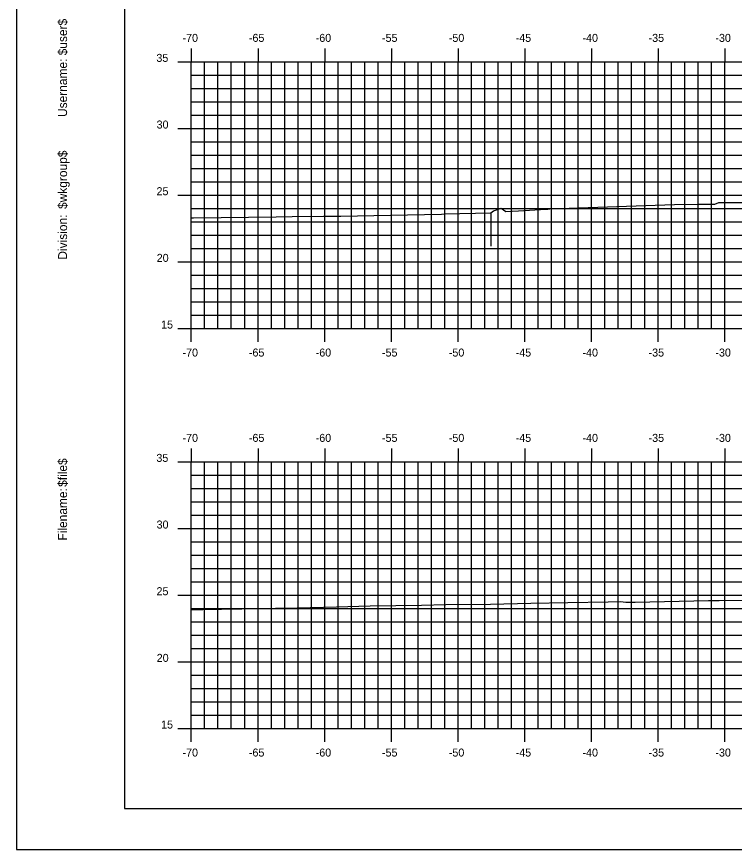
# Model space of a CAD drawing. Extents: x 1023237 to 1023407, y 394697 to 394807.
# Drawn here: x 1023236.6 to 1023290.4, y 394696.5 to 394759 of the extents above; entities that cross this region are included whole.
import ezdxf

# ---------------------------------------------------------------- set-up
doc = ezdxf.new("R2010")
doc.units = 0
for name, color, linetype in [('BORDER', 7, 'Continuous'), ('H_V ANNOTATION', 7, 'Continuous'), ('MAJOR', 7, 'Continuous'), ('MINOR', 7, 'Continuous'), ('PLOT BOUNDARY', 7, 'Continuous'), ('S_Roadway_Centerline', 7, 'Continuous'), ('S_Roadway_Edge_Pavement', 7, 'Continuous')]:
    doc.layers.add(name, color=color, linetype=linetype)

msp = doc.modelspace()

# ---------------------------------------------------------------- linework, layer by layer
at = {"layer": 'BORDER'}
for p, q in [((1023244.664, 394804.607), (1023244.664, 394699.607)), ((1023244.664, 394699.607), (1023404.664, 394699.607))]:
    msp.add_line(p, q, dxfattribs=at)
at = {"layer": 'MAJOR'}
for p, q in [((1023249.663, 394756.609), (1023249.663, 394755.607)), ((1023254.663, 394756.609), (1023254.663, 394755.607)), ((1023259.663, 394756.609), (1023259.663, 394755.607)), ((1023264.663, 394756.609), (1023264.663, 394755.607)), ((1023269.663, 394756.609), (1023269.663, 394755.607)), ((1023274.663, 394756.609), (1023274.663, 394755.607)), ((1023279.663, 394756.609), (1023279.663, 394755.607)), ((1023284.663, 394756.609), (1023284.663, 394755.607)), ((1023289.663, 394756.609), (1023289.663, 394755.607)), ((1023248.661, 394755.607), (1023249.663, 394755.607)), ((1023249.663, 394755.607), (1023389.663, 394755.607)), ((1023249.663, 394735.607), (1023249.663, 394755.607)), ((1023254.663, 394735.607), (1023254.663, 394755.607)), ((1023259.663, 394735.607), (1023259.663, 394755.607)), ((1023264.663, 394735.607), (1023264.663, 394755.607)), ((1023269.663, 394735.607), (1023269.663, 394755.607)), ((1023274.663, 394735.607), (1023274.663, 394755.607)), ((1023279.663, 394735.607), (1023279.663, 394755.607)), ((1023284.663, 394735.607), (1023284.663, 394755.607)), ((1023289.663, 394735.607), (1023289.663, 394755.607)), ((1023248.661, 394750.607), (1023249.663, 394750.607)), ((1023249.663, 394750.607), (1023389.663, 394750.607)), ((1023248.661, 394745.607), (1023249.663, 394745.607)), ((1023249.663, 394745.607), (1023389.663, 394745.607)), ((1023248.661, 394740.607), (1023249.663, 394740.607)), ((1023249.663, 394740.607), (1023389.663, 394740.607)), ((1023248.661, 394735.607), (1023249.663, 394735.607)), ((1023249.663, 394735.607), (1023389.663, 394735.607)), ((1023249.663, 394734.605), (1023249.663, 394735.607)), ((1023254.663, 394734.605), (1023254.663, 394735.607)), ((1023259.663, 394734.605), (1023259.663, 394735.607)), ((1023264.663, 394734.605), (1023264.663, 394735.607)), ((1023269.663, 394734.605), (1023269.663, 394735.607)), ((1023274.663, 394734.605), (1023274.663, 394735.607)), ((1023279.663, 394734.605), (1023279.663, 394735.607)), ((1023284.663, 394734.605), (1023284.663, 394735.607)), ((1023289.663, 394734.605), (1023289.663, 394735.607)), ((1023249.663, 394726.609), (1023249.663, 394725.607)), ((1023254.663, 394726.609), (1023254.663, 394725.607)), ((1023259.663, 394726.609), (1023259.663, 394725.607)), ((1023264.663, 394726.609), (1023264.663, 394725.607)), ((1023269.663, 394726.609), (1023269.663, 394725.607)), ((1023274.663, 394726.609), (1023274.663, 394725.607)), ((1023279.663, 394726.609), (1023279.663, 394725.607)), ((1023284.663, 394726.609), (1023284.663, 394725.607)), ((1023289.663, 394726.609), (1023289.663, 394725.607)), ((1023248.661, 394725.607), (1023249.663, 394725.607)), ((1023249.663, 394725.607), (1023389.663, 394725.607)), ((1023249.663, 394705.607), (1023249.663, 394725.607)), ((1023254.663, 394705.607), (1023254.663, 394725.607)), ((1023259.663, 394705.607), (1023259.663, 394725.607)), ((1023264.663, 394705.607), (1023264.663, 394725.607)), ((1023269.663, 394705.607), (1023269.663, 394725.607)), ((1023274.663, 394705.607), (1023274.663, 394725.607)), ((1023279.663, 394705.607), (1023279.663, 394725.607)), ((1023284.663, 394705.607), (1023284.663, 394725.607)), ((1023289.663, 394705.607), (1023289.663, 394725.607)), ((1023248.661, 394720.607), (1023249.663, 394720.607)), ((1023249.663, 394720.607), (1023389.663, 394720.607)), ((1023248.661, 394715.607), (1023249.663, 394715.607)), ((1023249.663, 394715.607), (1023389.663, 394715.607)), ((1023248.661, 394710.607), (1023249.663, 394710.607)), ((1023249.663, 394710.607), (1023389.663, 394710.607)), ((1023248.661, 394705.607), (1023249.663, 394705.607)), ((1023249.663, 394705.607), (1023389.663, 394705.607)), ((1023249.663, 394704.605), (1023249.663, 394705.607)), ((1023254.663, 394704.605), (1023254.663, 394705.607)), ((1023259.663, 394704.605), (1023259.663, 394705.607)), ((1023264.663, 394704.605), (1023264.663, 394705.607)), ((1023269.663, 394704.605), (1023269.663, 394705.607)), ((1023274.663, 394704.605), (1023274.663, 394705.607)), ((1023279.663, 394704.605), (1023279.663, 394705.607)), ((1023284.663, 394704.605), (1023284.663, 394705.607)), ((1023289.663, 394704.605), (1023289.663, 394705.607))]:
    msp.add_line(p, q, dxfattribs=at)
at = {"layer": 'MINOR'}
for p, q in [((1023250.663, 394735.607), (1023250.663, 394755.607)), ((1023251.663, 394735.607), (1023251.663, 394755.607)), ((1023252.663, 394735.607), (1023252.663, 394755.607)), ((1023253.663, 394735.607), (1023253.663, 394755.607)), ((1023255.663, 394735.607), (1023255.663, 394755.607)), ((1023256.663, 394735.607), (1023256.663, 394755.607)), ((1023257.663, 394735.607), (1023257.663, 394755.607)), ((1023258.663, 394735.607), (1023258.663, 394755.607)), ((1023260.663, 394735.607), (1023260.663, 394755.607)), ((1023261.663, 394735.607), (1023261.663, 394755.607)), ((1023262.663, 394735.607), (1023262.663, 394755.607)), ((1023263.663, 394735.607), (1023263.663, 394755.607)), ((1023265.663, 394735.607), (1023265.663, 394755.607)), ((1023266.663, 394735.607), (1023266.663, 394755.607)), ((1023267.663, 394735.607), (1023267.663, 394755.607)), ((1023268.663, 394735.607), (1023268.663, 394755.607)), ((1023270.663, 394735.607), (1023270.663, 394755.607)), ((1023271.663, 394735.607), (1023271.663, 394755.607)), ((1023272.663, 394735.607), (1023272.663, 394755.607)), ((1023273.663, 394735.607), (1023273.663, 394755.607)), ((1023275.663, 394735.607), (1023275.663, 394755.607)), ((1023276.663, 394735.607), (1023276.663, 394755.607)), ((1023277.663, 394735.607), (1023277.663, 394755.607)), ((1023278.663, 394735.607), (1023278.663, 394755.607)), ((1023280.663, 394735.607), (1023280.663, 394755.607)), ((1023281.663, 394735.607), (1023281.663, 394755.607)), ((1023282.663, 394735.607), (1023282.663, 394755.607)), ((1023283.663, 394735.607), (1023283.663, 394755.607)), ((1023285.663, 394735.607), (1023285.663, 394755.607)), ((1023286.663, 394735.607), (1023286.663, 394755.607)), ((1023287.663, 394735.607), (1023287.663, 394755.607)), ((1023288.663, 394735.607), (1023288.663, 394755.607)), ((1023249.663, 394754.607), (1023389.663, 394754.607)), ((1023249.663, 394754.607), (1023250.665, 394754.607)), ((1023249.663, 394753.607), (1023389.663, 394753.607)), ((1023249.663, 394753.607), (1023250.665, 394753.607)), ((1023249.663, 394752.607), (1023389.663, 394752.607)), ((1023249.663, 394752.607), (1023250.665, 394752.607)), ((1023249.663, 394751.607), (1023389.663, 394751.607)), ((1023249.663, 394751.607), (1023250.665, 394751.607)), ((1023249.663, 394749.607), (1023389.663, 394749.607)), ((1023249.663, 394749.607), (1023250.665, 394749.607)), ((1023249.663, 394748.607), (1023389.663, 394748.607)), ((1023249.663, 394748.607), (1023250.665, 394748.607)), ((1023249.663, 394747.607), (1023389.663, 394747.607)), ((1023249.663, 394747.607), (1023250.665, 394747.607)), ((1023249.663, 394746.607), (1023389.663, 394746.607)), ((1023249.663, 394746.607), (1023250.665, 394746.607)), ((1023249.663, 394744.607), (1023389.663, 394744.607)), ((1023249.663, 394744.607), (1023250.665, 394744.607)), ((1023249.663, 394743.607), (1023389.663, 394743.607)), ((1023249.663, 394743.607), (1023250.665, 394743.607)), ((1023249.663, 394742.607), (1023389.663, 394742.607)), ((1023249.663, 394742.607), (1023250.665, 394742.607)), ((1023249.663, 394741.607), (1023389.663, 394741.607)), ((1023249.663, 394741.607), (1023250.665, 394741.607)), ((1023249.663, 394739.607), (1023389.663, 394739.607)), ((1023249.663, 394739.607), (1023250.665, 394739.607)), ((1023249.663, 394738.607), (1023389.663, 394738.607)), ((1023249.663, 394738.607), (1023250.665, 394738.607)), ((1023249.663, 394737.607), (1023389.663, 394737.607)), ((1023249.663, 394737.607), (1023250.665, 394737.607)), ((1023249.663, 394736.607), (1023389.663, 394736.607)), ((1023249.663, 394736.607), (1023250.665, 394736.607)), ((1023250.663, 394705.607), (1023250.663, 394725.607)), ((1023251.663, 394705.607), (1023251.663, 394725.607)), ((1023252.663, 394705.607), (1023252.663, 394725.607)), ((1023253.663, 394705.607), (1023253.663, 394725.607)), ((1023255.663, 394705.607), (1023255.663, 394725.607)), ((1023256.663, 394705.607), (1023256.663, 394725.607)), ((1023257.663, 394705.607), (1023257.663, 394725.607)), ((1023258.663, 394705.607), (1023258.663, 394725.607)), ((1023260.663, 394705.607), (1023260.663, 394725.607)), ((1023261.663, 394705.607), (1023261.663, 394725.607)), ((1023262.663, 394705.607), (1023262.663, 394725.607)), ((1023263.663, 394705.607), (1023263.663, 394725.607)), ((1023265.663, 394705.607), (1023265.663, 394725.607)), ((1023266.663, 394705.607), (1023266.663, 394725.607)), ((1023267.663, 394705.607), (1023267.663, 394725.607)), ((1023268.663, 394705.607), (1023268.663, 394725.607)), ((1023270.663, 394705.607), (1023270.663, 394725.607)), ((1023271.663, 394705.607), (1023271.663, 394725.607)), ((1023272.663, 394705.607), (1023272.663, 394725.607)), ((1023273.663, 394705.607), (1023273.663, 394725.607)), ((1023275.663, 394705.607), (1023275.663, 394725.607)), ((1023276.663, 394705.607), (1023276.663, 394725.607)), ((1023277.663, 394705.607), (1023277.663, 394725.607)), ((1023278.663, 394705.607), (1023278.663, 394725.607)), ((1023280.663, 394705.607), (1023280.663, 394725.607)), ((1023281.663, 394705.607), (1023281.663, 394725.607)), ((1023282.663, 394705.607), (1023282.663, 394725.607)), ((1023283.663, 394705.607), (1023283.663, 394725.607)), ((1023285.663, 394705.607), (1023285.663, 394725.607)), ((1023286.663, 394705.607), (1023286.663, 394725.607)), ((1023287.663, 394705.607), (1023287.663, 394725.607)), ((1023288.663, 394705.607), (1023288.663, 394725.607)), ((1023249.663, 394724.607), (1023389.663, 394724.607)), ((1023249.663, 394724.607), (1023250.665, 394724.607)), ((1023249.663, 394723.607), (1023389.663, 394723.607)), ((1023249.663, 394723.607), (1023250.665, 394723.607)), ((1023249.663, 394722.607), (1023389.663, 394722.607)), ((1023249.663, 394722.607), (1023250.665, 394722.607)), ((1023249.663, 394721.607), (1023389.663, 394721.607)), ((1023249.663, 394721.607), (1023250.665, 394721.607)), ((1023249.663, 394719.607), (1023389.663, 394719.607)), ((1023249.663, 394719.607), (1023250.665, 394719.607)), ((1023249.663, 394718.607), (1023389.663, 394718.607)), ((1023249.663, 394718.607), (1023250.665, 394718.607)), ((1023249.663, 394717.607), (1023389.663, 394717.607)), ((1023249.663, 394717.607), (1023250.665, 394717.607)), ((1023249.663, 394716.607), (1023389.663, 394716.607)), ((1023249.663, 394716.607), (1023250.665, 394716.607)), ((1023249.663, 394714.607), (1023389.663, 394714.607)), ((1023249.663, 394714.607), (1023250.665, 394714.607)), ((1023249.663, 394713.607), (1023389.663, 394713.607)), ((1023249.663, 394713.607), (1023250.665, 394713.607)), ((1023249.663, 394712.607), (1023389.663, 394712.607)), ((1023249.663, 394712.607), (1023250.665, 394712.607)), ((1023249.663, 394711.607), (1023389.663, 394711.607)), ((1023249.663, 394711.607), (1023250.665, 394711.607)), ((1023249.663, 394709.607), (1023389.663, 394709.607)), ((1023249.663, 394709.607), (1023250.665, 394709.607)), ((1023249.663, 394708.607), (1023389.663, 394708.607)), ((1023249.663, 394708.607), (1023250.665, 394708.607)), ((1023249.663, 394707.607), (1023389.663, 394707.607)), ((1023249.663, 394707.607), (1023250.665, 394707.607)), ((1023249.663, 394706.607), (1023389.663, 394706.607)), ((1023249.663, 394706.607), (1023250.665, 394706.607))]:
    msp.add_line(p, q, dxfattribs=at)
at = {"layer": 'PLOT BOUNDARY'}
msp.add_lwpolyline([(1023236.57, 394696.548), (1023406.57, 394696.548), (1023406.57, 394806.548), (1023236.57, 394806.548)], close=True, dxfattribs=at)
at = {"layer": 'S_Roadway_Centerline'}
for points in [[(1023249.663, 394743.914), (1023249.831, 394743.917), (1023256.019, 394743.993), (1023257.232, 394744.008), (1023259.563, 394744.025), (1023260.861, 394744.03), (1023264.596, 394744.101), (1023268.413, 394744.195), (1023268.644, 394744.201), (1023272.123, 394744.286), (1023272.326, 394744.432), (1023272.895, 394744.631), (1023273.25, 394744.386), (1023274.203, 394744.447), (1023276.24, 394744.572), (1023276.324, 394744.567), (1023276.399, 394744.568), (1023276.534, 394744.58), (1023285.877, 394744.922), (1023287.679, 394744.946), (1023288.901, 394744.947), (1023289.211, 394745.057), (1023293.156, 394745.049)], [(1023249.663, 394714.506), (1023251.419, 394714.551), (1023251.637, 394714.555), (1023251.914, 394714.56), (1023255.005, 394714.614), (1023255.982, 394714.635), (1023257.595, 394714.673), (1023260.538, 394714.745), (1023263.083, 394714.799), (1023266.915, 394714.864), (1023268.755, 394714.899), (1023272.085, 394714.946), (1023275.113, 394715.003), (1023277.892, 394715.06), (1023280.918, 394715.113), (1023281.848, 394715.135), (1023282.248, 394715.091), (1023282.929, 394715.098), (1023288.435, 394715.204), (1023289.109, 394715.209), (1023289.138, 394715.209), (1023289.204, 394715.209), (1023289.236, 394715.208), (1023291.86, 394715.245)]]:
    msp.add_lwpolyline(points, dxfattribs=at)
at = {"layer": 'S_Roadway_Edge_Pavement'}
msp.add_line((1023272.123, 394744.286), (1023272.123, 394741.786), dxfattribs=at)

# ---------------------------------------------------------------- texts
at = {"layer": 'BORDER'}
for s, p in [('$user$', (1023240.348, 394756.098)), ('Username:', (1023240.348, 394751.474)), ('$wkgroup$', (1023240.348, 394744.576)), ('Division:', (1023240.348, 394740.773)), ('$file$', (1023240.348, 394723.732)), ('Filename:', (1023240.348, 394719.705))]:
    msp.add_text(s, height=0.6696, rotation=90, dxfattribs=at).set_placement(p)
at = {"layer": 'H_V ANNOTATION'}
for s, p in [('-70', (1023249.005, 394757.107)), ('-65', (1023253.981, 394757.107)), ('-60', (1023258.989, 394757.107)), ('-55', (1023263.96, 394757.107)), ('-50', (1023268.968, 394757.107)), ('-45', (1023273.981, 394757.107)), ('-40', (1023278.989, 394757.107)), ('-35', (1023283.944, 394757.107)), ('-30', (1023288.952, 394757.107)), ('35', (1023247.045, 394755.607)), ('30', (1023247.061, 394750.607)), ('25', (1023247.055, 394745.607)), ('20', (1023247.071, 394740.607)), ('15', (1023247.398, 394735.607)), ('-70', (1023249.005, 394733.507)), ('-65', (1023253.981, 394733.507)), ('-60', (1023258.989, 394733.507)), ('-55', (1023263.96, 394733.507)), ('-50', (1023268.968, 394733.507)), ('-45', (1023273.981, 394733.507)), ('-40', (1023278.989, 394733.507)), ('-35', (1023283.944, 394733.507)), ('-30', (1023288.952, 394733.507)), ('-70', (1023249.005, 394727.107)), ('-65', (1023253.981, 394727.107)), ('-60', (1023258.989, 394727.107)), ('-55', (1023263.96, 394727.107)), ('-50', (1023268.968, 394727.107)), ('-45', (1023273.981, 394727.107)), ('-40', (1023278.989, 394727.107)), ('-35', (1023283.944, 394727.107)), ('-30', (1023288.952, 394727.107)), ('35', (1023247.045, 394725.607)), ('30', (1023247.061, 394720.607)), ('25', (1023247.055, 394715.607)), ('20', (1023247.071, 394710.607)), ('15', (1023247.398, 394705.607)), ('-70', (1023249.005, 394703.507)), ('-65', (1023253.981, 394703.507)), ('-60', (1023258.989, 394703.507)), ('-55', (1023263.96, 394703.507)), ('-50', (1023268.968, 394703.507)), ('-45', (1023273.981, 394703.507)), ('-40', (1023278.989, 394703.507)), ('-35', (1023283.944, 394703.507)), ('-30', (1023288.952, 394703.507))]:
    msp.add_text(s, height=0.6, dxfattribs=at).set_placement(p)

doc.saveas('drawing.dxf')
